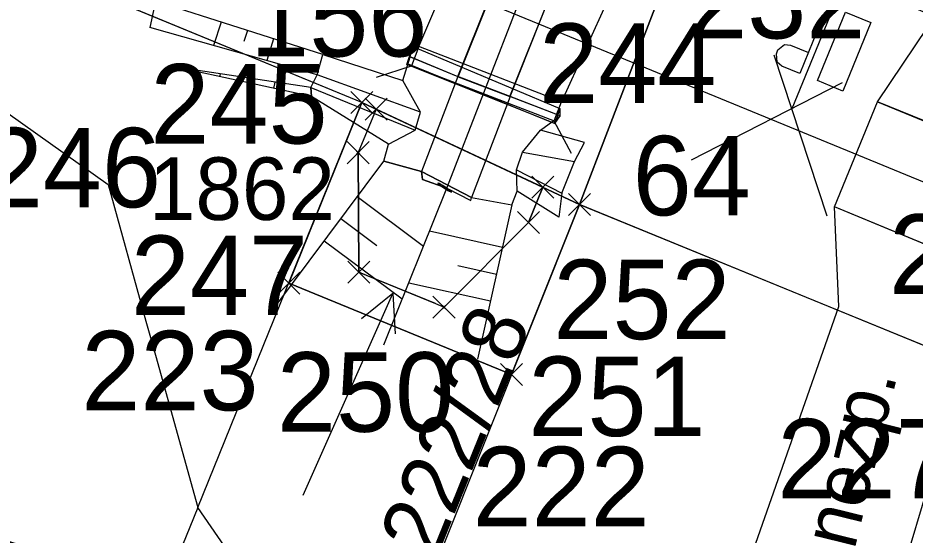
# Model space of a CAD drawing. Extents: x -779302 to -774398, y -1144902 to -1142831.
# Drawn here: x -776113.86 to -776089.47, y -1144239.97 to -1144225.91 of the extents above; entities that cross this region are included whole.
import ezdxf

# ---------------------------------------------------------------- set-up
doc = ezdxf.new("R2010")
doc.units = 0
for name, color, linetype in [('Dočasný zábor - do 1 roku', 7, 'Continuous'), ('Dočasný zábor - do 1 roku - ZPF', 7, 'Continuous'), ('Hranice parcel', 7, 'Continuous'), ('legenda I_5_2 - Vrstva 53', 7, 'Continuous'), ('Parcelní čísla', 7, 'Continuous'), ('SŽDC', 7, 'Continuous'), ('VBř', 7, 'Continuous'), ('Vnitřní kresba', 7, 'Continuous'), ('zjednodus_g_situ-seda - Vrstva 1', 7, 'Continuous'), ('zjednodus_g_situ-seda - Vrstva 19', 7, 'Continuous'), ('zjednodus_g_situ-seda - Vrstva 33', 7, 'Continuous'), ('zjednodus_g_situ-seda - Vrstva 4', 7, 'Continuous'), ('zjednodus_g_situ-seda - Vrstva 48', 7, 'Continuous'), ('zjednodus_g_situ-seda - Vrstva 49', 7, 'Continuous'), ('zjednodus_g_situ-seda - Vrstva 51', 7, 'Continuous'), ('Značky kultur', 7, 'Continuous')]:
    doc.layers.add(name, color=color, linetype=linetype)

msp = doc.modelspace()

# ---------------------------------------------------------------- linework, layer by layer
at = {"layer": 'Dočasný zábor - do 1 roku'}
for p, q in [((-776104.51, -1144228.21), (-776106.498, -1144233.119)), ((-776098.59, -1144230.98), (-776104.51, -1144228.21)), ((-776100.439, -1144235.603), (-776098.59, -1144230.98)), ((-776106.298, -1144233.319), (-776106.798, -1144232.819)), ((-776106.298, -1144232.919), (-776106.798, -1144233.419)), ((-776106.698, -1144233.319), (-776106.198, -1144232.819)), ((-776106.698, -1144232.919), (-776106.198, -1144233.419)), ((-776100.439, -1144235.603), (-776106.498, -1144233.119)), ((-776106.498, -1144233.119), (-776100.439, -1144235.603)), ((-776106.498, -1144233.119), (-776106.498, -1144233.119)), ((-776100.239, -1144235.803), (-776100.739, -1144235.303)), ((-776100.639, -1144235.803), (-776100.139, -1144235.303)), ((-776100.239, -1144235.403), (-776100.739, -1144235.903)), ((-776100.639, -1144235.403), (-776100.139, -1144235.903)), ((-776100.439, -1144235.603), (-776100.439, -1144235.603))]:
    msp.add_line(p, q, dxfattribs=at)
at = {"layer": 'Hranice parcel'}
for p, q in [((-776108.97, -1144239.22), (-776104.51, -1144228.21)), ((-776104.51, -1144228.21), (-776098.59, -1144230.98)), ((-776098.59, -1144230.98), (-776105.45, -1144248.13)), ((-776098.59, -1144230.98), (-776082.64, -1144237.51)), ((-776108.97, -1144239.22), (-776110.54, -1144243.08)), ((-776105.2, -1144244.66), (-776108.97, -1144239.22))]:
    msp.add_line(p, q, dxfattribs=at)
for points in [[(-776104.51, -1144228.21), (-776116.08, -1144223.44), (-776126.28, -1144219.86)], [(-776126.28, -1144219.86), (-776111.41, -1144230.44), (-776110.38, -1144234.15), (-776110.12, -1144235.08), (-776108.97, -1144239.22)], [(-776095.57, -1144223.11), (-776096.98, -1144226.78), (-776098.59, -1144230.98)]]:
    msp.add_lwpolyline(points, dxfattribs=at)
at = {"layer": 'legenda I_5_2 - Vrstva 53'}
for points in [[(-776431.42, -1144085.55), (-776339.24, -1144124.31), (-776253.98, -1144158.55), (-776237.42, -1144165.58), (-776113.15, -1144215.23), (-776109.59, -1144216.67), (-776105.05, -1144218.51), (-776101.21, -1144220.07), (-776096.42, -1144222.78), (-776095.57, -1144223.11), (-776096.98, -1144226.78), (-776098.59, -1144230.98), (-776104.51, -1144228.21), (-776116.08, -1144223.44), (-776126.28, -1144219.86), (-776203.96, -1144186.83), (-776252.27, -1144167.08), (-776325.22, -1144137.73), (-776342.13, -1144130.92), (-776434.38, -1144092.81)], [(-775971.84, -1144282.92), (-776064.26, -1144245.03), (-776082.64, -1144237.51), (-776098.59, -1144230.98), (-776096.98, -1144226.78), (-776095.57, -1144223.11), (-776061.24, -1144237.34), (-776053.07, -1144240.83), (-776052.08, -1144238.11), (-776022.68, -1144250.27)]]:
    msp.add_lwpolyline(points, dxfattribs=at)
at = {"layer": 'SŽDC'}
for p, q in [((-776104.31, -1144228.41), (-776104.81, -1144227.91)), ((-776104.31, -1144228.01), (-776104.81, -1144228.51)), ((-776104.71, -1144228.41), (-776104.21, -1144227.91)), ((-776104.71, -1144228.01), (-776104.21, -1144228.51)), ((-776104.51, -1144228.21), (-776104.51, -1144228.21)), ((-776098.39, -1144231.18), (-776098.89, -1144230.68)), ((-776098.79, -1144231.18), (-776098.29, -1144230.68)), ((-776098.39, -1144230.78), (-776098.89, -1144231.28)), ((-776098.79, -1144230.78), (-776098.29, -1144231.28)), ((-776098.59, -1144230.98), (-776098.59, -1144230.98))]:
    msp.add_line(p, q, dxfattribs=at)
for points in [[(-776098.59, -1144230.98), (-776104.51, -1144228.21), (-776116.08, -1144223.44), (-776126.28, -1144219.86), (-776203.96, -1144186.83), (-776252.27, -1144167.08), (-776325.22, -1144137.73), (-776342.13, -1144130.92), (-776434.38, -1144092.81), (-776527.2, -1144055.02), (-776604.66, -1144024.21), (-776606.85, -1144023.34), (-776609.89, -1144021.72), (-776627.91, -1144012.39), (-776712.36, -1143980.08), (-776747.29, -1143966.09), (-776893.47, -1143907.54), (-776959.34, -1143880.62), (-776970.83, -1143876.37), (-776982.48, -1143870.69)], [(-775971.84, -1144282.92), (-776064.26, -1144245.03), (-776082.64, -1144237.51), (-776098.59, -1144230.98)]]:
    msp.add_lwpolyline(points, dxfattribs=at)
at = {"layer": 'VBř'}
for p, q in [((-776103.924, -1144228.591), (-776104.424, -1144228.091)), ((-776103.924, -1144228.191), (-776104.424, -1144228.691)), ((-776104.324, -1144228.591), (-776103.824, -1144228.091)), ((-776104.324, -1144228.191), (-776103.824, -1144228.691)), ((-776104.124, -1144228.391), (-776104.608, -1144229.571)), ((-776104.124, -1144228.391), (-776104.608, -1144229.571)), ((-776099.59, -1144230.512), (-776104.124, -1144228.391)), ((-776104.124, -1144228.391), (-776104.124, -1144228.391)), ((-776104.408, -1144229.771), (-776104.908, -1144229.271)), ((-776104.408, -1144229.371), (-776104.908, -1144229.871)), ((-776104.808, -1144229.771), (-776104.308, -1144229.271)), ((-776104.808, -1144229.371), (-776104.308, -1144229.871)), ((-776104.589, -1144232.82), (-776104.608, -1144229.571)), ((-776104.608, -1144229.571), (-776104.589, -1144232.82)), ((-776104.608, -1144229.571), (-776104.608, -1144229.571)), ((-776099.39, -1144230.712), (-776099.89, -1144230.212)), ((-776099.79, -1144230.712), (-776099.29, -1144230.212)), ((-776099.39, -1144230.312), (-776099.89, -1144230.812)), ((-776099.79, -1144230.312), (-776099.29, -1144230.812)), ((-776099.59, -1144230.512), (-776099.982, -1144231.467)), ((-776099.982, -1144231.467), (-776099.59, -1144230.512)), ((-776099.59, -1144230.512), (-776099.59, -1144230.512)), ((-776099.782, -1144231.667), (-776100.282, -1144231.167)), ((-776100.182, -1144231.667), (-776099.682, -1144231.167)), ((-776099.782, -1144231.267), (-776100.282, -1144231.767)), ((-776100.182, -1144231.267), (-776099.682, -1144231.767)), ((-776102.276, -1144233.769), (-776099.982, -1144231.467)), ((-776102.276, -1144233.769), (-776099.982, -1144231.467)), ((-776099.982, -1144231.467), (-776099.982, -1144231.467)), ((-776104.389, -1144233.02), (-776104.889, -1144232.52)), ((-776104.389, -1144232.62), (-776104.889, -1144233.12)), ((-776104.789, -1144233.02), (-776104.289, -1144232.52)), ((-776104.789, -1144232.62), (-776104.289, -1144233.12)), ((-776104.358, -1144232.915), (-776104.589, -1144232.82)), ((-776104.589, -1144232.82), (-776102.508, -1144233.674)), ((-776104.589, -1144232.82), (-776104.589, -1144232.82)), ((-776102.508, -1144233.674), (-776104.358, -1144232.915)), ((-776102.076, -1144233.969), (-776102.576, -1144233.469)), ((-776102.076, -1144233.569), (-776102.576, -1144234.069)), ((-776102.476, -1144233.969), (-776101.976, -1144233.469)), ((-776102.476, -1144233.569), (-776101.976, -1144234.069)), ((-776102.508, -1144233.674), (-776102.276, -1144233.769)), ((-776102.508, -1144233.674), (-776102.508, -1144233.674)), ((-776102.508, -1144233.674), (-776102.276, -1144233.769)), ((-776102.276, -1144233.769), (-776102.276, -1144233.769))]:
    msp.add_line(p, q, dxfattribs=at)
at = {"layer": 'Vnitřní kresba'}
for p, q in [((-776102.96, -1144226.69), (-776101.57, -1144223.4)), ((-776097.6, -1144224.91), (-776099.08, -1144228.19)), ((-776102.96, -1144226.69), (-776103.16, -1144227.21)), ((-776099.08, -1144228.19), (-776102.96, -1144226.69)), ((-776104.112, -1144227.519), (-776103.161, -1144227.21)), ((-776103.16, -1144227.21), (-776099.28, -1144228.71)), ((-776099.28, -1144228.71), (-776099.08, -1144228.19)), ((-776098.811, -1144229.594), (-776099.28, -1144228.711))]:
    msp.add_line(p, q, dxfattribs=at)
at = {"layer": 'zjednodus_g_situ-seda - Vrstva 1'}
msp.add_lwpolyline([(-776044.897, -1144248.56), (-776062.233, -1144241.452), (-776078.991, -1144234.577), (-776085.488, -1144231.915), (-776091.151, -1144229.585), (-776100.22, -1144225.859), (-776117.47, -1144218.798), (-776139.186, -1144209.892), (-776163.331, -1144199.997), (-776180.566, -1144192.93), (-776204.576, -1144183.082), (-776229.267, -1144172.956), (-776243.873, -1144166.962), (-776268.358, -1144156.919), (-776287.099, -1144149.258), (-776305.754, -1144141.612), (-776329.891, -1144131.716), (-776350.499, -1144123.273), (-776368.759, -1144115.793), (-776392.07, -1144106.249), (-776411.789, -1144098.151)], dxfattribs=at)
at = {"layer": 'zjednodus_g_situ-seda - Vrstva 19'}
for p, q in [((-776102.198, -1144230.539), (-776098.522, -1144221.06)), ((-776101.901, -1144227.505), (-776100.298, -1144223.502)), ((-776101.891, -1144227.51), (-776100.3, -1144223.5)), ((-776100.483, -1144228.044), (-776098.904, -1144224.082)), ((-776100.479, -1144228.047), (-776098.904, -1144224.081)), ((-776103.279, -1144227.152), (-776099.267, -1144228.781)), ((-776105.901, -1144227.798), (-776105.723, -1144227.452)), ((-776100.479, -1144228.047), (-776101.901, -1144227.505)), ((-776101.891, -1144227.51), (-776100.483, -1144228.044)), ((-776099.119, -1144228.566), (-776099.119, -1144228.377)), ((-776099.267, -1144228.781), (-776099.119, -1144228.566)), ((-776099.074, -1144230.675), (-776098.728, -1144229.812))]:
    msp.add_line(p, q, dxfattribs=at)
for points in [[(-776099.123, -1144228.374), (-776099.267, -1144228.781), (-776103.291, -1144227.175), (-776103.123, -1144226.688), (-776099.123, -1144228.374)], [(-776103.279, -1144227.152), (-776103.199, -1144226.969), (-776103.134, -1144226.697)], [(-776103.123, -1144226.688), (-776103.134, -1144226.697)], [(-776102.912, -1144228.471), (-776105.723, -1144227.452), (-776105.567, -1144226.904), (-776103.394, -1144227.606)], [(-776101.901, -1144227.505), (-776102.891, -1144230.085), (-776103.915, -1144229.802), (-776103.783, -1144229.344), (-776103.06, -1144228.956), (-776102.912, -1144228.471), (-776103.394, -1144227.606), (-776103.199, -1144226.969), (-776101.901, -1144227.505)], [(-776101.901, -1144227.505), (-776101.891, -1144227.51), (-776103.199, -1144226.969)], [(-776103.279, -1144227.152), (-776103.291, -1144227.175)], [(-776103.783, -1144229.344), (-776105.875, -1144228.048), (-776105.901, -1144227.798), (-776103.06, -1144228.956)], [(-776099.119, -1144228.566), (-776100.483, -1144228.044), (-776100.479, -1144228.047)], [(-776100.479, -1144228.047), (-776101.525, -1144230.786), (-776100.429, -1144230.988), (-776100.284, -1144230.615), (-776100.307, -1144230.034), (-776100.139, -1144229.559), (-776099.656, -1144228.958), (-776099.119, -1144228.566), (-776100.479, -1144228.047)], [(-776099.119, -1144228.377), (-776099.123, -1144228.374)], [(-776100.139, -1144229.559), (-776098.728, -1144229.812), (-776098.455, -1144229.291), (-776099.656, -1144228.958)], [(-776099.267, -1144228.781), (-776099.267, -1144228.781)], [(-776101.525, -1144230.786), (-776102.891, -1144230.085), (-776102.865, -1144230.3), (-776102.198, -1144230.539), (-776101.551, -1144230.871), (-776101.525, -1144230.786)], [(-776100.307, -1144230.034), (-776099.074, -1144230.675), (-776099.157, -1144231.322), (-776100.284, -1144230.615)]]:
    msp.add_lwpolyline(points, dxfattribs=at)
for major_axis, start_param, end_param in [((-0.188, 0.123), 4.439093, 9.296924), ((0.188, -0.123), 4.882774, 7.580686)]:
    msp.add_ellipse((-776102.258, -1144230.52), major_axis=major_axis, ratio=0.080036, start_param=start_param, end_param=end_param, dxfattribs=at)
at = {"layer": 'zjednodus_g_situ-seda - Vrstva 33'}
msp.add_lwpolyline([(-776091.431, -1144227.896), (-776092.12, -1144227.613), (-776091.355, -1144225.75), (-776090.666, -1144226.033)], close=True, dxfattribs=at)
msp.add_lwpolyline([(-776092.128, -1144226.259), (-776092.605, -1144227.419), (-776093.087, -1144227.221), (-776093.213, -1144227.112), (-776093.238, -1144226.882), (-776093.196, -1144226.78), (-776093.015, -1144226.63), (-776092.852, -1144226.648), (-776092.369, -1144226.846)], dxfattribs=at)
at = {"layer": 'zjednodus_g_situ-seda - Vrstva 4'}
for p, q in [((-776091.485, -1144225.123), (-776092.821, -1144228.376)), ((-776091.858, -1144231.294), (-776093.303, -1144226.917)), ((-776091.453, -1144227.677), (-776095.558, -1144229.774))]:
    msp.add_line(p, q, dxfattribs=at)
msp.add_lwpolyline([(-776084.942, -1144230.47), (-776086.109, -1144233.339), (-776091.655, -1144231.045), (-776090.486, -1144228.187), (-776084.942, -1144230.47)], dxfattribs=at)
at = {"layer": 'zjednodus_g_situ-seda - Vrstva 48'}
for p, q in [((-776108.338, -1144226.02), (-776108.541, -1144226.657)), ((-776107.623, -1144226.248), (-776107.721, -1144226.554)), ((-776106.909, -1144226.476), (-776107.097, -1144227.065)), ((-776108.367, -1144227.507), (-776108.35, -1144227.43)), ((-776107.634, -1144227.666), (-776107.62, -1144227.604)), ((-776106.901, -1144227.825), (-776106.863, -1144227.653)), ((-776104.633, -1144230.764), (-776102.831, -1144232.109)), ((-776105.082, -1144231.365), (-776104.101, -1144232.097)), ((-776100.687, -1144232.147), (-776102.668, -1144231.705)), ((-776105.53, -1144231.966), (-776103.411, -1144233.548)), ((-776100.851, -1144232.879), (-776101.901, -1144232.644)), ((-776101.014, -1144233.611), (-776103.236, -1144233.115))]:
    msp.add_line(p, q, dxfattribs=at)
at = {"layer": 'zjednodus_g_situ-seda - Vrstva 49'}
for p, q in [((-776105.723, -1144227.452), (-776110.276, -1144226.168)), ((-776105.901, -1144227.798), (-776109.56, -1144227.248)), ((-776106.956, -1144233.877), (-776103.915, -1144229.802))]:
    msp.add_line(p, q, dxfattribs=at)
for points in [[(-776105.723, -1144227.452), (-776105.567, -1144226.904), (-776110.119, -1144225.451), (-776110.276, -1144226.168)], [(-776105.901, -1144227.798), (-776105.875, -1144228.048), (-776109.56, -1144227.248)], [(-776103.915, -1144229.802), (-776102.891, -1144230.085), (-776101.525, -1144230.786), (-776100.429, -1144230.988), (-776101.366, -1144235.188)], [(-776103.915, -1144234.799), (-776102.198, -1144230.539), (-776102.865, -1144230.3), (-776102.891, -1144230.085)], [(-776102.198, -1144230.539), (-776101.551, -1144230.871), (-776101.525, -1144230.786)]]:
    msp.add_lwpolyline(points, dxfattribs=at)
at = {"layer": 'zjednodus_g_situ-seda - Vrstva 51'}
for p, q in [((-776084.942, -1144230.47), (-776090.486, -1144228.187)), ((-776086.109, -1144233.339), (-776091.655, -1144231.045))]:
    msp.add_line(p, q, dxfattribs=at)
for points in [[(-776090.486, -1144228.187), (-776087.751, -1144224.11), (-776085.209, -1144219.157)], [(-776096.155, -1144243.391), (-776093.799, -1144240.19), (-776091.54, -1144233.756), (-776091.655, -1144231.045)], [(-776090.889, -1144244.587), (-776087.974, -1144234.836), (-776086.109, -1144233.339)]]:
    msp.add_lwpolyline(points, dxfattribs=at)
at = {"layer": 'Značky kultur'}
for p, q in [((-776106.105, -1144238.878), (-776103.665, -1144233.397)), ((-776103.665, -1144233.397), (-776104.521, -1144234.086)), ((-776103.665, -1144233.397), (-776103.604, -1144234.494))]:
    msp.add_line(p, q, dxfattribs=at)

# ---------------------------------------------------------------- texts
at = {"layer": 'Dočasný zábor - do 1 roku'}
for s, p in [('223', (-776112.136, -1144236.575)), ('222', (-776101.501, -1144239.725))]:
    msp.add_text(s, height=2.16, dxfattribs=at).set_placement(p)
at = {"layer": 'Dočasný zábor - do 1 roku - ZPF'}
msp.add_text('232', height=2.16, dxfattribs=at).set_placement((-776095.637, -1144226.466))
at = {"layer": 'Parcelní čísla'}
msp.add_text('1862', height=1.7, dxfattribs=at).set_placement((-776110.3, -1144231.4))
for s, rotation, p in [('1222/28', 68, (-776102.971, -1144241.828)), ('1222/27', 343, (-776121.709, -1144239.578))]:
    msp.add_text(s, height=1.7, rotation=rotation, dxfattribs=at).set_placement(p)
at = {"layer": 'SŽDC'}
for s, p in [('156', (-776107.546, -1144226.956)), ('64', (-776097.146, -1144231.275))]:
    msp.add_text(s, height=2.16, dxfattribs=at).set_placement(p)
at = {"layer": 'VBř'}
for s, p in [('244', (-776099.689, -1144228.217)), ('245', (-776110.259, -1144229.323)), ('246', (-776114.79, -1144231.057)), ('226', (-776090.173, -1144233.409)), ('247', (-776110.791, -1144233.985)), ('252', (-776099.301, -1144234.64)), ('250', (-776106.82, -1144237.157)), ('251', (-776099.982, -1144237.274)), ('227', (-776093.21, -1144238.97))]:
    msp.add_text(s, height=2.16, dxfattribs=at).set_placement(p)
at = {"layer": 'zjednodus_g_situ-seda - Vrstva 51'}
msp.add_text('nezp.', height=1.5, rotation=76.1794, dxfattribs=at).set_placement((-776091.118, -1144240.394))

doc.saveas('drawing.dxf')
